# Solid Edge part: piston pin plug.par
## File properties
Author: Deepak Maini
Template: Normal.par
Last saved by: Robert a Rhodes jr
Revision: 2
Application: Solid Edge
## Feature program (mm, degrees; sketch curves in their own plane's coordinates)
sketch for "unnamed Protrusion 1" plane through (0, 0, 0) normal (0, 0, 1) x-axis (1, 0, 0)
  circle centre (0, 0) radius 5.5
extrude "unnamed Protrusion 1" add finite 12 along -normal
sketch for "unnamed Protrusion 2" plane through (0, 0, 0) normal (0, 0, 1) x-axis (0, 1, 0)
  circle centre (0, 0) radius 11
extrude "unnamed Protrusion 2" add finite 3 along +normal
fillet "unnamed Round 1"
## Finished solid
Body 1: solid body, 6 faces, 5 edges, 0 vertices.
  Faces by surface: plane 3, cylinder 2, torus 1
  Edges by curve: circle 5
Bounding box of the edges (mm; curved faces can reach further): 22.000 x 22.000 x 15.000, from (-11, -11, -12) to (11, 11, 3).
Cylindrical faces by radius (mm): R5.5 x1, R11 x1
Toroidal faces (ring radius, tube radius in mm): R9 r2 x1
Planar faces by outward normal: +z 1, -z 2
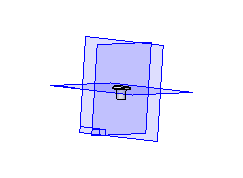
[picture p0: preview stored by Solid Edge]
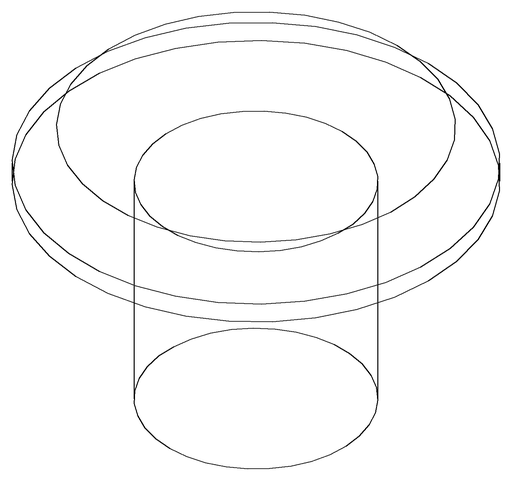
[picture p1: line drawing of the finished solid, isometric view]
